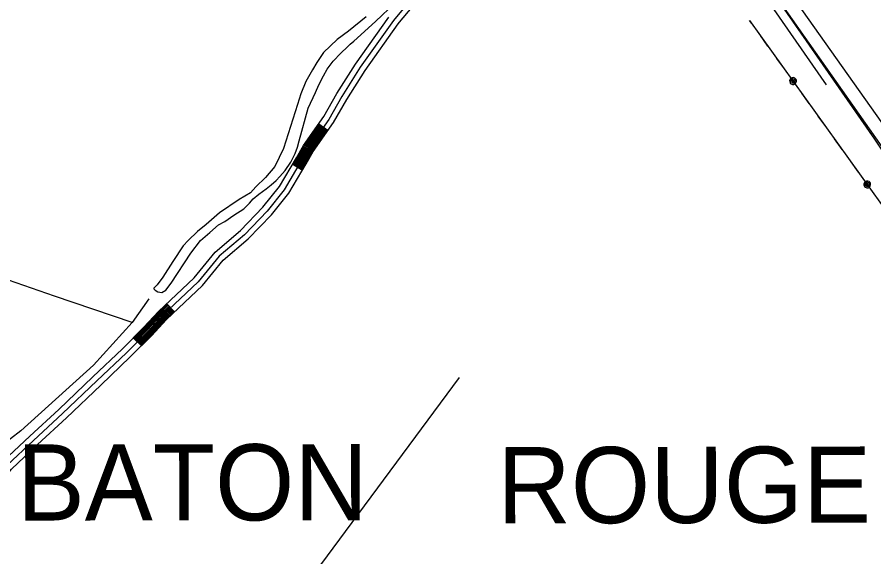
# Model space of a CAD drawing. Extents: x 3271442 to 3309282, y 752266 to 777610.
# Drawn here: x 3277086 to 3279334, y 764466 to 765883 of the extents above; entities that cross this region are included whole.
import ezdxf

# ---------------------------------------------------------------- set-up
doc = ezdxf.new("R2010")
doc.units = 0
for name, color, linetype in [('V-RAIL-TRAK', 7, 'Continuous'), ('V-ROAD-CNTR', 7, 'Continuous'), ('V-TOPO-GNAM-IDEN', 7, 'Continuous'), ('V-TOPO-SHOR', 7, 'Continuous'), ('V-UTIL-LINE', 7, 'Continuous')]:
    doc.layers.add(name, color=color, linetype=linetype)

msp = doc.modelspace()

# ---------------------------------------------------------------- linework, layer by layer
at = {"layer": 'V-RAIL-TRAK'}
msp.add_lwpolyline([(3276291.2, 769941.4), (3276466.8, 769687.9), (3276599.6, 769496.8), (3276819.8, 769181), (3277020, 768893.5), (3277174.1, 768671), (3277374.2, 768384.3), (3277564.8, 768110.1), (3277710.5, 767901.4), (3277897.5, 767631.8), (3278109.9, 767326.4), (3278338.2, 766998.2), (3278559.3, 766680.6), (3278649.4, 766551), (3278673.9, 766515.2), (3278727.5, 766439.3), (3278938.1, 766135.1), (3279106.8, 765892.9), (3279335.7, 765562.9), (3279510.8, 765302.4)], dxfattribs=at)
at = {"layer": 'V-ROAD-CNTR'}
for p, q in [((3277877.4, 765603), (3277902, 765585.8)), ((3277809.1, 765497.1), (3277834.9, 765481.8)), ((3277478.5, 765131), (3277499.2, 765109.3)), ((3277390.7, 765041.5), (3277412, 765020.3))]:
    msp.add_line(p, q, dxfattribs=at)
for points in [[(3279396.3, 767088.1), (3279311.8, 766936), (3279231.3, 766810.2), (3279190.2, 766758.1), (3279128.9, 766703.8), (3279075.4, 766662.5), (3279033.4, 766642.6), (3278837.3, 766598.5), (3278753.8, 766563.8), (3278701, 766529.1), (3278647.1, 766460.1), (3278527.7, 766291.8), (3278475.4, 766228.3), (3278399.1, 766165.1), (3278294.2, 766083.6), (3278195.6, 766002.3), (3278129.9, 765942.8), (3278073.6, 765874.2)], [(3278085.2, 765864.7), (3278140.8, 765932.4), (3278205.4, 765991), (3278303.5, 766071.9), (3278408.4, 766153.4), (3278486.1, 766217.7), (3278539.6, 766282.7), (3278659.1, 766451.1), (3278711.4, 766517.9), (3278760.8, 766550.5), (3278841.9, 766584.1), (3279038.3, 766628.3), (3279083.2, 766649.6), (3279138.5, 766692.2), (3279201.2, 766747.7), (3279243.5, 766801.5), (3279324.7, 766928.3), (3279409.4, 767080.7)], [(3278896.6, 766194.4), (3279207.3, 765753.2), (3279382, 765504.2), (3279510.2, 765320.4), (3279619.3, 765148.7), (3279740.6, 764957.9), (3279844.1, 764790.1), (3279937, 764634.6), (3280041, 764460.4), (3280130.2, 764309.9), (3280239.6, 764110.5), (3280361.9, 763885.2), (3280539.4, 763549), (3280924.1, 762814.5), (3281160.7, 762359.8), (3281314.6, 762065), (3281497.6, 761722.5), (3281661.2, 761410.7), (3281877.3, 760997.6)], [(3278073.6, 765874.2), (3277986.3, 765751.8), (3277938, 765674.8), (3277903.7, 765614.5), (3277850.5, 765538.2), (3277831.7, 765505.9), (3277786.8, 765430.1), (3277741.9, 765374.1), (3277682.3, 765312.2), (3277616, 765255.6), (3277561.2, 765188.8), (3277467.3, 765099.7), (3277428.6, 765058.2), (3277372.6, 765002.2), (3277295.4, 764928.4), (3277205.3, 764842.6), (3277129.3, 764772.1), (3277060.2, 764707.1), (3276994, 764622.9), (3276938.2, 764527.3), (3276864.3, 764397.1)], [(3276895, 764481.5), (3276925.2, 764534.8), (3276981.6, 764631.3), (3277049.1, 764717.3), (3277119.1, 764783), (3277195.1, 764853.5), (3277285, 764939.2), (3277362.1, 765012.9), (3277417.8, 765068.6), (3277456.7, 765110.3), (3277550.2, 765199), (3277605.2, 765266.1), (3277672, 765323.2), (3277730.7, 765384), (3277774.4, 765438.7), (3277818.8, 765513.5), (3277837.8, 765546.3), (3277891, 765622.5), (3277925.1, 765682.4), (3277973.9, 765760.2), (3278061.4, 765883)], [(3276877.8, 764390.5), (3276951.2, 764519.8), (3277006.4, 764614.4), (3277071.3, 764697), (3277139.5, 764761.1), (3277215.6, 764831.6), (3277305.7, 764917.5), (3277383, 764991.4), (3277439.4, 765047.8), (3277478, 765089.1), (3277572.2, 765178.5), (3277626.7, 765245.1), (3277692.6, 765301.3), (3277753.2, 765364.1), (3277799.2, 765421.6), (3277844.7, 765498.3), (3277863.1, 765530.2), (3277916.4, 765606.5), (3277950.9, 765667.1), (3277998.8, 765743.5), (3278085.8, 765865.5)], [(3277811.6, 765495.6), (3277821.4, 765512), (3277840.3, 765544.7), (3277879.8, 765601.3)], [(3277814.2, 765494), (3277824, 765510.5), (3277842.9, 765543.1), (3277882.3, 765599.5)], [(3277816.8, 765492.5), (3277826.6, 765508.9), (3277845.4, 765541.5), (3277884.8, 765597.8)], [(3277819.4, 765491), (3277829.1, 765507.4), (3277847.9, 765539.9), (3277887.2, 765596.1)], [(3277822, 765489.4), (3277831.7, 765505.9), (3277850.5, 765538.2), (3277889.7, 765594.4)], [(3277824.5, 765487.9), (3277834.3, 765504.4), (3277853, 765536.6), (3277892.1, 765592.7)], [(3277827.1, 765486.4), (3277836.9, 765502.9), (3277855.5, 765535), (3277894.6, 765591)], [(3277829.7, 765484.9), (3277839.5, 765501.4), (3277858.1, 765533.4), (3277897.1, 765589.2)], [(3277832.3, 765483.3), (3277842.1, 765499.8), (3277860.6, 765531.8), (3277899.5, 765587.5)], [(3277392.9, 765039.4), (3277420, 765066.5), (3277458.8, 765108.2), (3277480.6, 765128.8)], [(3277395, 765037.3), (3277422.1, 765064.4), (3277460.9, 765106), (3277482.7, 765126.7)], [(3277397.1, 765035.2), (3277424.3, 765062.4), (3277463.1, 765103.9), (3277484.7, 765124.5)], [(3277399.2, 765033.1), (3277426.5, 765060.3), (3277465.2, 765101.8), (3277486.8, 765122.3)], [(3277401.4, 765030.9), (3277428.6, 765058.2), (3277467.3, 765099.7), (3277488.9, 765120.1)], [(3277403.5, 765028.8), (3277430.8, 765056.1), (3277469.5, 765097.6), (3277490.9, 765118)], [(3277405.6, 765026.7), (3277432.9, 765054), (3277471.6, 765095.5), (3277493, 765115.8)], [(3277407.7, 765024.6), (3277435.1, 765051.9), (3277473.7, 765093.4), (3277495.1, 765113.6)], [(3277409.8, 765022.4), (3277437.3, 765049.8), (3277475.9, 765091.2), (3277497.1, 765111.4)]]:
    msp.add_lwpolyline(points, dxfattribs=at)
at = {"layer": 'V-TOPO-SHOR'}
msp.add_line((3279209.4, 765705.6), (3279003.9, 766003.1), dxfattribs=at)
for points in [[(3278721.5, 766504.6), (3279054.9, 766030.4), (3279475.2, 765435.4), (3279543.7, 765333.2), (3279571.2, 765309.8), (3279589.4, 765272.7), (3279685.2, 765119.4)], [(3278002, 765884), (3277955.6, 765846.6), (3277925.9, 765824.4), (3277890.1, 765790.4), (3277872.2, 765764.6), (3277861.4, 765744.6), (3277843.4, 765714), (3277830.2, 765682.2), (3277821.7, 765653.9), (3277785.3, 765538.4), (3277762.4, 765491.4), (3277737.4, 765462), (3277712.3, 765437.4), (3277698, 765422.2), (3277668.3, 765404.7), (3277617.3, 765369.7), (3277581.6, 765339.2), (3277558.9, 765320.5), (3277535.1, 765297.1), (3277522, 765283), (3277494.5, 765241.9), (3277468.2, 765200.7), (3277453.8, 765180.8), (3277444.3, 765171.4), (3277444.3, 765170.2), (3277447.8, 765166.6), (3277454.8, 765161.8), (3277465.5, 765160.6), (3277476.1, 765166.4), (3277490.5, 765185.2), (3277541.9, 765263.9), (3277567, 765296.8), (3277592, 765317.9), (3277614.6, 765337.8), (3277631.2, 765347.1), (3277655, 765363.4), (3277681.1, 765379.8), (3277695.4, 765395), (3277705, 765406.7), (3277720.5, 765418.4), (3277739.5, 765432.5), (3277752.6, 765443), (3277765.7, 765454.7), (3277775.2, 765465.3), (3277789.5, 765480.5), (3277803.9, 765502.8), (3277815.9, 765525.2), (3277821.9, 765541.7), (3277825.6, 765558.2), (3277849.9, 765644.2), (3277869.2, 765685.4), (3277877.6, 765705.5), (3277889.6, 765729), (3277899.2, 765746.6), (3277914.8, 765767.8), (3277935, 765788.9), (3277952.9, 765805.3), (3277960, 765812.3), (3277969.5, 765820.5), (3278026.7, 765872), (3278077.9, 765921.2)], [(3277388, 765082), (3277183.9, 765150.6), (3276941.6, 765234.7), (3276439.3, 765402.2), (3276118.3, 765510.5)], [(3277431.3, 765143.8), (3277388, 765082), (3277286.6, 764969.3), (3277095.7, 764797.6), (3276986.4, 764713), (3276918.6, 764618.8), (3276846, 764503.9)], [(3279666.7, 763991.9), (3278238.5, 763971.4), (3277882.6, 763974.3), (3277688.6, 763975.9), (3277586.8, 763972.1), (3277601.5, 764064.4), (3278246.4, 764937.2)]]:
    msp.add_lwpolyline(points, dxfattribs=at)
at = {"layer": 'V-UTIL-LINE'}
for points in [[(3279012.8, 765867.5), (3279007.8, 765874.5)], [(3279007.8, 765874.5), (3279354.3, 765391.5), (3279687.8, 764906.1), (3279981.8, 764398.1), (3280293.1, 763854.3), (3280575.1, 763339.8), (3280779.7, 762774.9), (3281005.9, 762220.7), (3281173.7, 761647.9), (3281355.9, 761062.2), (3281532.2, 760488.9), (3281714, 759910), (3281890.6, 759335.6), (3282074.7, 758762.4), (3282253.7, 758183.8), (3282418.2, 757643.6)], [(3279056, 765807.4), (3279036.1, 765835)], [(3279099.1, 765747.3), (3279079.3, 765774.9)], [(3279121.8, 765715.6), (3279120.9, 765712.9), (3279123.1, 765713.5), (3279124, 765716.1), (3279122, 765718.2), (3279119.2, 765716.4), (3279118.3, 765711.8), (3279122, 765709.7), (3279126.5, 765711.4), (3279127.5, 765715.8), (3279125.8, 765719.9), (3279121.1, 765721.2), (3279116.4, 765718.2), (3279114.5, 765710.3), (3279117.1, 765707.9), (3279120.4, 765706.7), (3279123.9, 765706.8), (3279127.1, 765708.2), (3279129.5, 765710.8), (3279130.7, 765714.1), (3279130.6, 765717.6), (3279129.1, 765720.8), (3279126.6, 765723.2), (3279123.3, 765724.4), (3279119.8, 765724.3), (3279116.6, 765722.9), (3279114.2, 765720.3), (3279112.9, 765717), (3279113.1, 765713.5), (3279114.5, 765710.3)], [(3279164.4, 765656.2), (3279144.6, 765683.9)], [(3279207.5, 765596.1), (3279187.7, 765623.7)], [(3279250.7, 765536), (3279230.8, 765563.6)], [(3279293.8, 765475.9), (3279274, 765503.5)], [(3279316.5, 765444.2), (3279315.6, 765441.5), (3279317.8, 765442.1), (3279318.7, 765444.7), (3279316.7, 765446.9), (3279313.8, 765445), (3279313, 765440.4), (3279316.7, 765438.3), (3279321.2, 765440), (3279322.2, 765444.5), (3279320.5, 765448.6), (3279315.8, 765449.8), (3279311.1, 765446.9), (3279309.2, 765438.9), (3279311.8, 765436.5), (3279315.1, 765435.3), (3279318.6, 765435.4), (3279321.8, 765436.9), (3279324.2, 765439.4), (3279325.4, 765442.7), (3279325.3, 765446.2), (3279323.8, 765449.4), (3279321.3, 765451.8), (3279318, 765453.1), (3279314.5, 765452.9), (3279311.3, 765451.5), (3279308.9, 765448.9), (3279307.6, 765445.6), (3279307.8, 765442.1), (3279309.2, 765438.9)]]:
    msp.add_lwpolyline(points, dxfattribs=at)

# ---------------------------------------------------------------- texts
at = {"layer": 'V-TOPO-GNAM-IDEN'}
for s, rotation, p in [('BATON', 0.0366, (3277085.3, 764561.7)), ('ROUGE', 0.108, (3278345.9, 764554.3))]:
    msp.add_text(s, height=200, rotation=rotation, dxfattribs=at).set_placement(p)

doc.saveas('drawing.dxf')
